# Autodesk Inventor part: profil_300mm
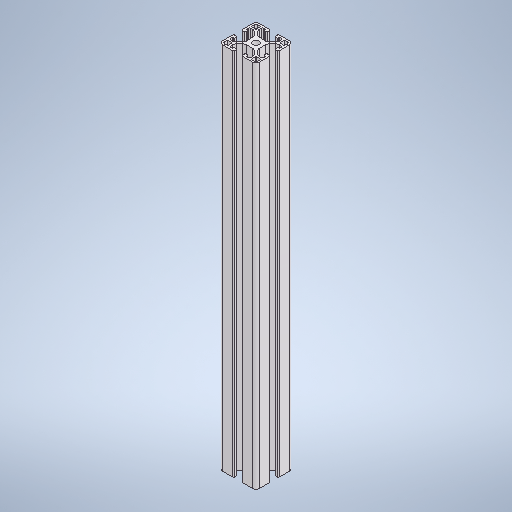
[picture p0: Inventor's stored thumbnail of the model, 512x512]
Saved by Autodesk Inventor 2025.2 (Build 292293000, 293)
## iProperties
Company: CADClick - www.CADClick.com
Created: 2025-04
Part Number: profil_300mm
Material: Generic
Description: STEP AP214
Document SubType Name: Modeling
Designer: Jarni
Authority: unknown authorization
Density: 1 g/cm^3
Appearance: Default
Preprocessor: Spatial InterOp 3D
Title: cctmp_E645AAE7-4D4E-402E-9FB8-C5FCD92D0650_2025_04_11_13_18_13_0061_50468..stp
Author: KiM GmbH
Revision Number: NONE
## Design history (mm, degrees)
feature "item_0041906_Profil 6 30x30 leicht_L=1000_1"
thicken "Thicken1" dims "d2" = 700, "d3" = 700
body "Solid1"
